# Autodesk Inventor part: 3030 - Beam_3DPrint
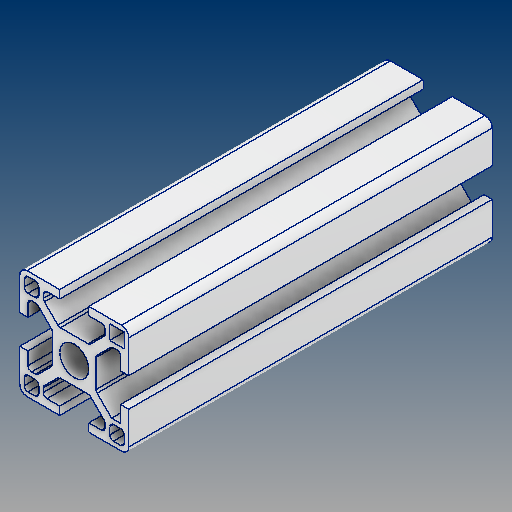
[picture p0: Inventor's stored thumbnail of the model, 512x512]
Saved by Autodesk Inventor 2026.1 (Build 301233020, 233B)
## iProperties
Created: 2026-02
Part Number: 3030 - Beam_3DPrint
Material: Generic
Document SubType Name: Modeling
Designer: shane
Density: 1 g/cm^3
Appearance: Default
Author: shane
Created: 2024-09
Part Number: 3030 - Beam
Material: Aluminum 6061
Density: 2.7 g/cm^3
Appearance: Aluminum - Flat
Sending System: SOLIDWORKS 2015
Last Saved Date: 2024-09-24
last saved by: Ahmed Sayed
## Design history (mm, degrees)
workplane "Work Plane1"
sketch "Sketch1"
  geometry: L1 (0.25, 11)-(-2, 11); L2 (-2, 11)-(-2, 2); L3 (0, 0)-(9, 0); L4 (9, 0)-(9, 2.25); L5 (9, 2.25)-(5.5, 2.25); L6 (4.5, 3.25)-(4.5, 4.318); L7 (4.793, 5.025)-(8.475, 8.707); L8 (9.182, 9)-(16.818, 9); L9 (17.525, 8.707)-(21.207, 5.025); L10 (21.5, 4.318)-(21.5, 3.25); L11 (20.5, 2.25)-(17, 2.25); L12 (17, 2.25)-(17, 0); L13 (17, 0)-(26, 0); L14 (28, 2)-(28, 11); L15 (28, 11)-(25.75, 11); L16 (25.75, 11)-(25.75, 6.5); L17 (25.75, 6.5)-(23.268, 6.5); L18 (23.268, 6.5)-(19.293, 10.475); L19 (19, 11.182)-(19, 18.818); L20 (19.293, 19.525)-(22.975, 23.207); L21 (23.682, 23.5)-(24.75, 23.5); L22 (25.75, 22.5)-(25.75, 19); L23 (25.75, 19)-(28, 19); L24 (28, 19)-(28, 28); L25 (26, 30)-(17, 30); L26 (17, 30)-(17, 27.75); L27 (17, 27.75)-(20.5, 27.75); L28 (21.5, 26.75)-(21.5, 25.682); L29 (21.207, 24.975)-(17.525, 21.293); L30 (16.818, 21)-(9.182, 21); L31 (8.475, 21.293)-(4.793, 24.975); L32 (4.5, 25.682)-(4.5, 26.75); L33 (5.5, 27.75)-(9, 27.75); L34 (9, 27.75)-(9, 30); L35 (9, 30)-(0, 30); L36 (-2, 28)-(-2, 19); L37 (-2, 19)-(0.25, 19); L38 (0.25, 19)-(0.25, 22.5); L39 (1.25, 23.5)-(2.318, 23.5); L40 (3.025, 23.207)-(6.707, 19.525); L41 (7, 18.818)-(7, 11.182); L42 (6.707, 10.475)-(3.025, 6.793); L43 (2.318, 6.5)-(1.25, 6.5); L44 (0.25, 7.5)-(0.25, 11); L45 (26.75, 24.75)-(26.75, 28.75); L46 (22.75, 24.75)-(26.75, 24.75); L47 (22.75, 28.75)-(22.75, 24.75); L48 (26.75, 28.75)-(22.75, 28.75); L49 (2.25, 28.75)-(0.25, 28.75); L50 (3.25, 25.75)-(3.25, 27.75); L51 (0.25, 24.75)-(2.25, 24.75); L52 (-0.75, 27.75)-(-0.75, 25.75); L53 (0.25, 1.25)-(2.25, 1.25); L54 (-0.75, 4.25)-(-0.75, 2.25); L55 (2.25, 5.25)-(0.25, 5.25); L56 (3.25, 2.25)-(3.25, 4.25); L57 (22.75, 4.25)-(22.75, 2.25); L58 (25.75, 5.25)-(23.75, 5.25); L59 (26.75, 2.25)-(26.75, 4.25); L60 (23.75, 1.25)-(25.75, 1.25); C1 r 4 at (13, 15); A1 r 2 centre (0, 2) between (-2, 2) and (0, 0); A2 r 1 centre (5.5, 3.25) between (4.5, 3.25) and (5.5, 2.25); A3 r 1 centre (5.5, 4.318) between (4.793, 5.025) and (4.5, 4.318); A4 r 1 centre (9.182, 8) between (9.182, 9) and (8.475, 8.707); A5 r 1 centre (16.818, 8) between (17.525, 8.707) and (16.818, 9); A6 r 1 centre (20.5, 4.318) between (21.5, 4.318) and (21.207, 5.025); A7 r 1 centre (20.5, 3.25) between (20.5, 2.25) and (21.5, 3.25); A8 r 2 centre (26, 2) between (26, 0) and (28, 2); A9 r 1 centre (20, 11.182) between (19, 11.182) and (19.293, 10.475); A10 r 1 centre (20, 18.818) between (19.293, 19.525) and (19, 18.818); A11 r 1 centre (23.682, 22.5) between (23.682, 23.5) and (22.975, 23.207); A12 r 1 centre (24.75, 22.5) between (25.75, 22.5) and (24.75, 23.5); A13 r 2 centre (26, 28) between (28, 28) and (26, 30); A14 r 1 centre (20.5, 26.75) between (21.5, 26.75) and (20.5, 27.75); A15 r 1 centre (20.5, 25.682) between (21.207, 24.975) and (21.5, 25.682); A16 r 1 centre (16.818, 22) between (16.818, 21) and (17.525, 21.293); A17 r 1 centre (9.182, 22) between (8.475, 21.293) and (9.182, 21); A18 r 1 centre (5.5, 25.682) between (4.5, 25.682) and (4.793, 24.975); A19 r 1 centre (5.5, 26.75) between (5.5, 27.75) and (4.5, 26.75); A20 r 2 centre (0, 28) between (0, 30) and (-2, 28); A21 r 1 centre (1.25, 22.5) between (1.25, 23.5) and (0.25, 22.5); A22 r 1 centre (2.318, 22.5) between (3.025, 23.207) and (2.318, 23.5); A23 r 1 centre (6, 18.818) between (7, 18.818) and (6.707, 19.525); A24 r 1 centre (6, 11.182) between (6.707, 10.475) and (7, 11.182); A25 r 1 centre (2.318, 7.5) between (2.318, 6.5) and (3.025, 6.793); A26 r 1 centre (1.25, 7.5) between (0.25, 7.5) and (1.25, 6.5); A27 r 1 centre (2.25, 27.75) between (3.25, 27.75) and (2.25, 28.75); A28 r 1 centre (2.25, 25.75) between (2.25, 24.75) and (3.25, 25.75); A29 r 1 centre (0.25, 25.75) between (-0.75, 25.75) and (0.25, 24.75); A30 r 1 centre (0.25, 27.75) between (0.25, 28.75) and (-0.75, 27.75); A31 r 1 centre (0.25, 2.25) between (-0.75, 2.25) and (0.25, 1.25); A32 r 1 centre (0.25, 4.25) between (0.25, 5.25) and (-0.75, 4.25); A33 r 1 centre (2.25, 4.25) between (3.25, 4.25) and (2.25, 5.25); A34 r 1 centre (2.25, 2.25) between (2.25, 1.25) and (3.25, 2.25); A35 r 1 centre (23.75, 4.25) between (23.75, 5.25) and (22.75, 4.25); A36 r 1 centre (25.75, 4.25) between (26.75, 4.25) and (25.75, 5.25); A37 r 1 centre (25.75, 2.25) between (25.75, 1.25) and (26.75, 2.25); A38 r 1 centre (23.75, 2.25) between (22.75, 2.25) and (23.75, 1.25); 1 further point
  constraints: 39 centre point, 2 end point
extrude "Extrusion1" new body sketch "Sketch1" distance "d0" = 100; taper "d1" = 0 deg
body "Solid2"
